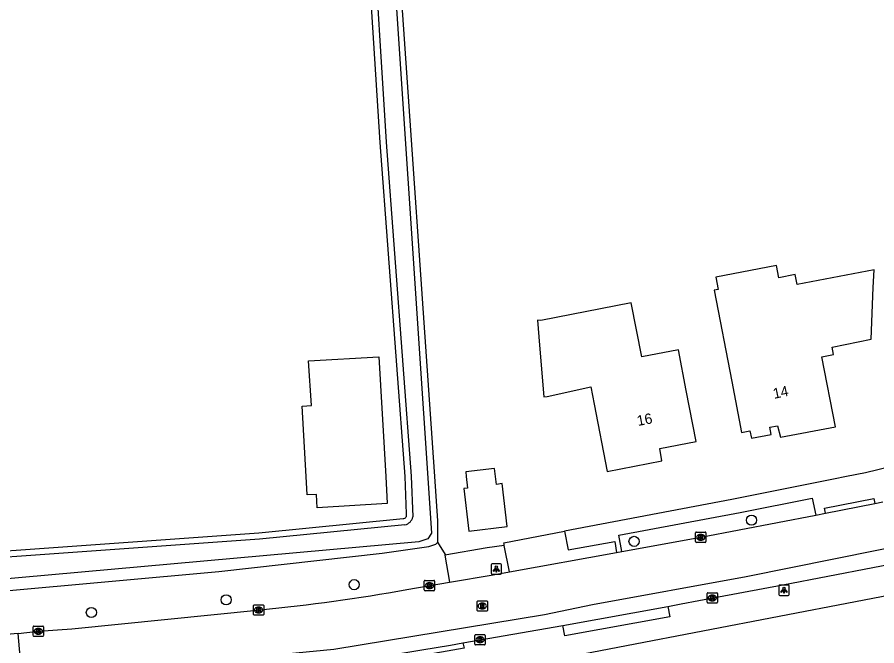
# Model space of a CAD drawing. Extents: x 161772 to 163123, y 383092 to 383917.
# Drawn here: x 162121.3 to 162204.2, y 383483.7 to 383544.3 of the extents above; entities that cross this region are included whole.
import ezdxf

# ---------------------------------------------------------------- set-up
doc = ezdxf.new("R2010")
doc.units = 0
for name, color, linetype in [('IMGEO_Boom', 7, 'Continuous'), ('IMGEO_Erf', 7, 'Continuous'), ('IMGEO_Groenvoorziening', 7, 'Continuous'), ('IMGEO_Kolk', 7, 'Continuous'), ('IMGEO_Lichtpunt', 7, 'Continuous'), ('IMGEO_Pand', 7, 'Continuous'), ('IMGEO_Pand_nummerreeks', 7, 'Continuous'), ('IMGEO_Rijbaan_lokaal_gesloten', 7, 'Continuous'), ('IMGEO_Rijbaan_lokaal_open', 7, 'Continuous'), ('IMGEO_Rioolput', 7, 'Continuous'), ('IMGEO_Voetpad_gesloten', 7, 'Continuous'), ('IMGEO_Voetpad_open', 7, 'Continuous'), ('IMGEO_Waterloop', 7, 'Continuous')]:
    doc.layers.add(name, color=color, linetype=linetype)

msp = doc.modelspace()

# ---------------------------------------------------------------- linework, layer by layer
at = {"layer": 'IMGEO_Boom'}
for centre in [(162192.143, 383495.789), (162180.807, 383493.753), (162153.81, 383489.576), (162141.449, 383488.119), (162128.443, 383486.899)]:
    msp.add_circle(centre, 0.489, dxfattribs=at)
at = {"layer": 'IMGEO_Erf'}
for points in [[(162161.876, 383493.674), (162161.877, 383495.743), (162161.582, 383500), (162158.081, 383550.584), (162157.485, 383556.946), (162155.147, 383589.879), (162154.233, 383609.363)], [(162158.844, 383496.393), (162158.71, 383500), (162156.297, 383532.223), (162154.911, 383554.445), (162150.941, 383605.06)], [(162069.536, 383488.799), (162096.809, 383491.155), (162144.603, 383494.579), (162158.53, 383495.946)]]:
    msp.add_lwpolyline(points, dxfattribs=at)
msp.add_arc((162158.525, 383496.283), 0.337, 270.78389, 19.04303, dxfattribs=at)
at = {"layer": 'IMGEO_Groenvoorziening'}
for points in [[(162062.506, 383483.909), (162085.683, 383486.129), (162109.132, 383487.972), (162140.737, 383490.84), (162156.508, 383492.599), (162160.992, 383493.243), (162161.691, 383493.467), (162161.876, 383493.674)], [(162162.551, 383492.413), (162162.614, 383492.483), (162161.876, 383493.674)]]:
    msp.add_lwpolyline(points, dxfattribs=at)
at = {"layer": 'IMGEO_Kolk'}
for p, q in [((162186.747, 383493.724), (162186.747, 383494.576)), ((162186.822, 383494.65), (162187.674, 383494.65)), ((162187.235, 383494.43), (162187.26, 383494.43)), ((162187.748, 383494.576), (162187.748, 383493.724)), ((162187.674, 383493.65), (162186.822, 383493.65)), ((162187.258, 383493.87), (162187.233, 383493.87)), ((162160.566, 383489.065), (162160.566, 383489.917)), ((162160.641, 383489.991), (162161.493, 383489.991)), ((162161.054, 383489.771), (162161.079, 383489.771)), ((162161.567, 383489.917), (162161.567, 383489.065)), ((162161.493, 383488.991), (162160.641, 383488.991)), ((162161.077, 383489.211), (162161.052, 383489.211)), ((162187.858, 383487.873), (162187.858, 383488.725)), ((162187.933, 383488.799), (162188.785, 383488.799)), ((162188.346, 383488.579), (162188.371, 383488.579)), ((162188.859, 383488.725), (162188.859, 383487.873)), ((162144.157, 383487.633), (162145.009, 383487.633)), ((162188.785, 383487.799), (162187.933, 383487.799)), ((162188.369, 383488.019), (162188.344, 383488.019)), ((162144.082, 383486.707), (162144.082, 383487.559)), ((162144.593, 383486.853), (162144.568, 383486.853)), ((162144.57, 383487.413), (162144.595, 383487.413)), ((162145.083, 383487.559), (162145.083, 383486.707)), ((162145.009, 383486.633), (162144.157, 383486.633)), ((162122.826, 383484.657), (162122.826, 383485.509)), ((162122.901, 383485.583), (162123.753, 383485.583)), ((162123.314, 383485.363), (162123.339, 383485.363)), ((162123.827, 383485.509), (162123.827, 383484.657)), ((162123.753, 383484.583), (162122.901, 383484.583)), ((162123.337, 383484.803), (162123.312, 383484.803)), ((162165.445, 383483.833), (162165.445, 383484.685)), ((162165.52, 383484.759), (162166.372, 383484.759)), ((162165.933, 383484.539), (162165.958, 383484.539)), ((162166.446, 383484.685), (162166.446, 383483.833)), ((162166.372, 383483.759), (162165.52, 383483.759)), ((162165.956, 383483.979), (162165.931, 383483.979))]:
    msp.add_line(p, q, dxfattribs=at)
for points in [[(162186.747, 383493.724), (162186.747, 383494.576)], [(162186.822, 383494.65), (162187.674, 383494.65)], [(162187.068, 383494.35), (162187.191, 383494.35), (162187.191, 383494.199), (162187.321, 383494.35), (162187.485, 383494.35), (162187.339, 383494.199), (162187.492, 383493.95), (162187.34, 383493.95), (162187.255, 383494.114), (162187.191, 383494.047), (162187.191, 383493.95), (162187.068, 383493.95), (162187.068, 383494.35)], [(162187.748, 383494.576), (162187.748, 383493.724)], [(162187.674, 383493.65), (162186.822, 383493.65)], [(162160.566, 383489.065), (162160.566, 383489.917)], [(162160.641, 383489.991), (162161.493, 383489.991)], [(162160.887, 383489.691), (162161.01, 383489.691), (162161.01, 383489.54), (162161.14, 383489.691), (162161.304, 383489.691), (162161.158, 383489.54), (162161.311, 383489.291), (162161.159, 383489.291), (162161.074, 383489.455), (162161.01, 383489.388), (162161.01, 383489.291), (162160.887, 383489.291), (162160.887, 383489.691)], [(162161.567, 383489.917), (162161.567, 383489.065)], [(162161.493, 383488.991), (162160.641, 383488.991)], [(162187.858, 383487.873), (162187.858, 383488.725)], [(162187.933, 383488.799), (162188.785, 383488.799)], [(162188.179, 383488.499), (162188.302, 383488.499), (162188.302, 383488.348), (162188.432, 383488.499), (162188.596, 383488.499), (162188.45, 383488.348), (162188.603, 383488.099), (162188.451, 383488.099), (162188.366, 383488.263), (162188.302, 383488.196), (162188.302, 383488.099), (162188.179, 383488.099), (162188.179, 383488.499)], [(162188.859, 383488.725), (162188.859, 383487.873)], [(162144.157, 383487.633), (162145.009, 383487.633)], [(162188.785, 383487.799), (162187.933, 383487.799)], [(162144.082, 383486.707), (162144.082, 383487.559)], [(162144.403, 383487.333), (162144.526, 383487.333), (162144.526, 383487.182), (162144.656, 383487.333), (162144.82, 383487.333), (162144.674, 383487.182), (162144.827, 383486.933), (162144.675, 383486.933), (162144.59, 383487.097), (162144.526, 383487.03), (162144.526, 383486.933), (162144.403, 383486.933), (162144.403, 383487.333)], [(162145.083, 383487.559), (162145.083, 383486.707)], [(162145.009, 383486.633), (162144.157, 383486.633)], [(162122.826, 383484.657), (162122.826, 383485.509)], [(162122.901, 383485.583), (162123.753, 383485.583)], [(162123.147, 383485.283), (162123.27, 383485.283), (162123.27, 383485.132), (162123.4, 383485.283), (162123.564, 383485.283), (162123.418, 383485.132), (162123.571, 383484.883), (162123.419, 383484.883), (162123.334, 383485.047), (162123.27, 383484.98), (162123.27, 383484.883), (162123.147, 383484.883), (162123.147, 383485.283)], [(162123.827, 383485.509), (162123.827, 383484.657)], [(162123.753, 383484.583), (162122.901, 383484.583)], [(162165.445, 383483.833), (162165.445, 383484.685)], [(162165.52, 383484.759), (162166.372, 383484.759)], [(162165.766, 383484.459), (162165.889, 383484.459), (162165.889, 383484.308), (162166.019, 383484.459), (162166.183, 383484.459), (162166.037, 383484.308), (162166.19, 383484.059), (162166.038, 383484.059), (162165.953, 383484.223), (162165.889, 383484.156), (162165.889, 383484.059), (162165.766, 383484.059), (162165.766, 383484.459)], [(162166.446, 383484.685), (162166.446, 383483.833)], [(162166.372, 383483.759), (162165.52, 383483.759)]]:
    msp.add_lwpolyline(points, dxfattribs=at)
for centre, start, end in [((162186.824, 383494.574), 91.55205, 178.44795), ((162186.824, 383494.574), 91.55205, 178.44795), ((162187.672, 383494.574), 1.55205, 88.44795), ((162187.672, 383494.574), 1.55205, 88.44795), ((162186.824, 383493.726), 181.55205, 268.44795), ((162186.824, 383493.726), 181.55205, 268.44795), ((162187.672, 383493.726), 271.55205, 358.44795), ((162187.672, 383493.726), 271.55205, 358.44795), ((162160.643, 383489.915), 91.55205, 178.44795), ((162160.643, 383489.915), 91.55205, 178.44795), ((162161.491, 383489.915), 1.55205, 88.44795), ((162161.491, 383489.915), 1.55205, 88.44795), ((162160.643, 383489.067), 181.55205, 268.44795), ((162160.643, 383489.067), 181.55205, 268.44795), ((162161.491, 383489.067), 271.55205, 358.44795), ((162161.491, 383489.067), 271.55205, 358.44795), ((162187.935, 383488.723), 91.55205, 178.44795), ((162187.935, 383488.723), 91.55205, 178.44795), ((162188.783, 383488.723), 1.55205, 88.44795), ((162188.783, 383488.723), 1.55205, 88.44795), ((162144.159, 383487.557), 91.55205, 178.44795), ((162144.159, 383487.557), 91.55205, 178.44795), ((162145.007, 383487.557), 1.55205, 88.44795), ((162145.007, 383487.557), 1.55205, 88.44795), ((162187.935, 383487.875), 181.55205, 268.44795), ((162187.935, 383487.875), 181.55205, 268.44795), ((162188.783, 383487.875), 271.55205, 358.44795), ((162188.783, 383487.875), 271.55205, 358.44795), ((162144.159, 383486.709), 181.55205, 268.44795), ((162144.159, 383486.709), 181.55205, 268.44795), ((162145.007, 383486.709), 271.55205, 358.44795), ((162145.007, 383486.709), 271.55205, 358.44795), ((162122.903, 383485.507), 91.55205, 178.44795), ((162122.903, 383485.507), 91.55205, 178.44795), ((162123.751, 383485.507), 1.55205, 88.44795), ((162123.751, 383485.507), 1.55205, 88.44795), ((162122.903, 383484.659), 181.55205, 268.44795), ((162122.903, 383484.659), 181.55205, 268.44795), ((162123.751, 383484.659), 271.55205, 358.44795), ((162123.751, 383484.659), 271.55205, 358.44795), ((162165.522, 383484.683), 91.55205, 178.44795), ((162165.522, 383484.683), 91.55205, 178.44795), ((162166.37, 383484.683), 1.55205, 88.44795), ((162166.37, 383484.683), 1.55205, 88.44795), ((162165.522, 383483.835), 181.55205, 268.44795), ((162165.522, 383483.835), 181.55205, 268.44795), ((162166.37, 383483.835), 271.55205, 358.44795), ((162166.37, 383483.835), 271.55205, 358.44795)]:
    msp.add_arc(centre, 0.0765, start, end, dxfattribs=at)
for centre, major_axis, ratio, start_param, end_param in [((162187.234, 383494.15), (-0.387, 0.002), 0.722429, 4.712389, 7.853982), ((162187.259, 383494.15), (-0.39, 0.002), 0.717154, 1.570796, 4.712389), ((162161.053, 383489.491), (-0.387, 0.002), 0.722429, 4.712389, 7.853982), ((162161.078, 383489.491), (-0.39, 0.002), 0.717154, 1.570796, 4.712389), ((162188.345, 383488.299), (-0.387, 0.002), 0.722429, 4.712389, 7.853982), ((162188.37, 383488.299), (-0.39, 0.002), 0.717154, 1.570796, 4.712389), ((162144.569, 383487.133), (-0.387, 0.002), 0.722429, 4.712389, 7.853982), ((162144.594, 383487.133), (-0.39, 0.002), 0.717154, 1.570796, 4.712389), ((162123.313, 383485.083), (-0.387, 0.002), 0.722429, 4.712389, 7.853982), ((162123.338, 383485.083), (-0.39, 0.002), 0.717154, 1.570796, 4.712389), ((162165.932, 383484.259), (-0.387, 0.002), 0.722429, 4.712389, 7.853982), ((162165.957, 383484.259), (-0.39, 0.002), 0.717154, 1.570796, 4.712389)]:
    msp.add_ellipse(centre, major_axis=major_axis, ratio=ratio, start_param=start_param, end_param=end_param, dxfattribs=at)
at = {"layer": 'IMGEO_Lichtpunt'}
for p, q in [((162167.02, 383491.479), (162167.02, 383490.672)), ((162167.02, 383491.479), (162167.02, 383490.672)), ((162167.922, 383491.574), (162167.114, 383491.574)), ((162167.922, 383491.574), (162167.114, 383491.574)), ((162168.016, 383490.672), (162168.016, 383491.479)), ((162168.016, 383490.672), (162168.016, 383491.479)), ((162167.114, 383490.578), (162167.922, 383490.578)), ((162167.114, 383490.578), (162167.922, 383490.578)), ((162194.775, 383489.447), (162194.775, 383488.64)), ((162194.775, 383489.447), (162194.775, 383488.64)), ((162195.677, 383489.542), (162194.869, 383489.542)), ((162195.677, 383489.542), (162194.869, 383489.542)), ((162195.771, 383488.64), (162195.771, 383489.447)), ((162195.771, 383488.64), (162195.771, 383489.447)), ((162194.869, 383488.546), (162195.677, 383488.546)), ((162194.869, 383488.546), (162195.677, 383488.546))]:
    msp.add_line(p, q, dxfattribs=at)
for points in [[(162167.394, 383491.143), (162167.433, 383491.115), (162167.245, 383490.853), (162167.207, 383490.88), (162167.394, 383491.143)], [(162167.496, 383491.095), (162167.543, 383491.095), (162167.543, 383490.773), (162167.496, 383490.773), (162167.496, 383491.095)], [(162167.606, 383491.115), (162167.644, 383491.142), (162167.831, 383490.88), (162167.792, 383490.852), (162167.606, 383491.115)], [(162195.149, 383489.111), (162195.188, 383489.083), (162195, 383488.821), (162194.962, 383488.848), (162195.149, 383489.111)], [(162195.251, 383489.063), (162195.298, 383489.063), (162195.298, 383488.741), (162195.251, 383488.741), (162195.251, 383489.063)], [(162195.361, 383489.083), (162195.399, 383489.11), (162195.586, 383488.848), (162195.547, 383488.82), (162195.361, 383489.083)]]:
    msp.add_lwpolyline(points, dxfattribs=at)
for centre in [(162167.519, 383491.277), (162195.274, 383489.245)]:
    msp.add_circle(centre, 0.0994, dxfattribs=at)
for centre, start, end in [((162167.114, 383491.479), 90, 180), ((162167.114, 383491.479), 90, 180), ((162167.922, 383491.479), 0, 90), ((162167.922, 383491.479), 0, 90), ((162167.114, 383490.672), 180, 270), ((162167.114, 383490.672), 180, 270), ((162167.922, 383490.672), 270, 0), ((162167.922, 383490.672), 270, 360), ((162194.869, 383489.447), 90, 180), ((162194.869, 383489.447), 90, 180), ((162195.677, 383489.447), 0, 90), ((162195.677, 383489.447), 0, 90), ((162194.869, 383488.64), 180, 270), ((162194.869, 383488.64), 180, 270), ((162195.677, 383488.64), 270, 0), ((162195.677, 383488.64), 270, 360)]:
    msp.add_arc(centre, 0.0946, start, end, dxfattribs=at)
at = {"layer": 'IMGEO_Pand'}
for points in [[(162203.893, 383518.235), (162203.962, 383519.946), (162196.537, 383518.512), (162196.349, 383519.481), (162194.771, 383519.177), (162194.542, 383520.361), (162188.713, 383519.235), (162188.94, 383518.049), (162188.538, 383517.972), (162190.237, 383509.166), (162191.185, 383504.256), (162191.973, 383504.406), (162192.152, 383503.708), (162194.049, 383504.071), (162193.909, 383504.783), (162194.64, 383504.894), (162194.94, 383503.789), (162200.24, 383504.802), (162198.917, 383511.548), (162200.059, 383511.769), (162199.928, 383512.488), (162203.69, 383513.239), (162203.893, 383518.235)], [(162176.966, 383506.995), (162178.211, 383500.507), (162183.504, 383501.529), (162183.298, 383502.704), (162186.803, 383503.392), (162185.849, 383508.301), (162185.086, 383512.224), (162181.554, 383511.537), (162180.541, 383516.748), (162171.827, 383515.057), (162171.503, 383515.098), (162171.697, 383512.672), (162172.096, 383507.687), (162172.418, 383507.711), (162176.65, 383508.642), (162176.966, 383506.995)], [(162149.154, 383500), (162148.774, 383506.794), (162149.672, 383506.849), (162149.406, 383511.15), (162156.178, 383511.559), (162156.85, 383500), (162157, 383497.415), (162150.232, 383496.997), (162150.152, 383498.284), (162149.253, 383498.228), (162149.154, 383500)], [(162164.377, 383498.843), (162164.861, 383494.748), (162168.577, 383495.187), (162168.09, 383499.318), (162167.531, 383499.252), (162167.444, 383500), (162167.352, 383500.783), (162164.569, 383500.454), (162164.622, 383500), (162164.753, 383498.888), (162164.377, 383498.843)]]:
    msp.add_lwpolyline(points, dxfattribs=at)
at = {"layer": 'IMGEO_Rijbaan_lokaal_gesloten'}
for points in [[(162199.296, 383496.468), (162204.046, 383497.404)], [(162204.046, 383497.404), (162204.798, 383497.552)], [(162179.624, 383492.766), (162187.245, 383494.148), (162198.338, 383496.284)], [(162198.338, 383496.284), (162199.296, 383496.468)], [(162213.84, 383494.742), (162208.551, 383493.75), (162191.634, 383490.333), (162176.787, 383487.642), (162172.161, 383486.674), (162151.828, 383483.337), (162127.505, 383480.969), (162121.767, 383480.433)], [(162168.781, 383490.815), (162179.124, 383492.675)], [(162179.124, 383492.675), (162179.624, 383492.766)], [(162163.009, 383489.813), (162167.216, 383490.539), (162168.781, 383490.815)], [(162158.883, 383489.1), (162163.009, 383489.813)], [(162121.373, 383484.872), (162123.327, 383485.081), (162126.573, 383485.331), (162144.748, 383487.15)]]:
    msp.add_lwpolyline(points, dxfattribs=at)
msp.add_arc((162126.484, 383671.743), 185.494, 275.65044, 280.05893, dxfattribs=at)
at = {"layer": 'IMGEO_Rijbaan_lokaal_open'}
for points in [[(162121.373, 383484.872), (162101.898, 383483.2)], [(162121.767, 383480.433), (162121.373, 383484.872)]]:
    msp.add_lwpolyline(points, dxfattribs=at)
at = {"layer": 'IMGEO_Rioolput'}
for p, q in [((162165.664, 383487.095), (162165.664, 383487.947)), ((162165.739, 383488.021), (162166.591, 383488.021)), ((162166.152, 383487.801), (162166.177, 383487.801)), ((162166.665, 383487.947), (162166.665, 383487.095)), ((162166.591, 383487.021), (162165.739, 383487.021)), ((162166.175, 383487.241), (162166.15, 383487.241))]:
    msp.add_line(p, q, dxfattribs=at)
for points in [[(162165.664, 383487.095), (162165.664, 383487.947)], [(162165.739, 383488.021), (162166.591, 383488.021)], [(162166.253, 383487.719), (162166.001, 383487.721), (162166.001, 383487.321)], [(162166.179, 383487.64), (162166.125, 383487.64), (162166.125, 383487.559)], [(162166.665, 383487.947), (162166.665, 383487.095)], [(162166.591, 383487.021), (162165.739, 383487.021)], [(162166.001, 383487.321), (162166.125, 383487.321), (162166.125, 383487.483), (162166.136, 383487.483)], [(162166.125, 383487.559), (162166.177, 383487.559)], [(162166.183, 383487.454), (162166.254, 383487.321), (162166.394, 383487.321), (162166.329, 383487.447)]]:
    msp.add_lwpolyline(points, dxfattribs=at)
for centre, radius, start, end in [((162165.741, 383487.945), 0.0765, 91.55205, 178.44795), ((162165.741, 383487.945), 0.0765, 91.55205, 178.44795), ((162166.185, 383487.544), 0.0964, 77.00612, 93.18647), ((162166.199, 383487.601), 0.0378, 276.66336, 79.67722), ((162166.252, 383487.609), 0.109, 350.36119, 89.41601), ((162166.589, 383487.945), 0.0765, 1.55205, 88.44795), ((162166.589, 383487.945), 0.0765, 1.55205, 88.44795), ((162165.741, 383487.097), 0.0765, 181.55205, 268.44795), ((162165.741, 383487.097), 0.0765, 181.55205, 268.44795), ((162166.135, 383487.43), 0.0533, 26.02933, 88.69889), ((162166.161, 383487.748), 0.19, 274.7715, 282.96867), ((162166.25, 383487.609), 0.112, 277.58423, 350.98172), ((162166.234, 383487.394), 0.108, 29.51342, 73.79051), ((162166.589, 383487.097), 0.0765, 271.55205, 358.44795), ((162166.589, 383487.097), 0.0765, 271.55205, 358.44795)]:
    msp.add_arc(centre, radius, start, end, dxfattribs=at)
for centre, major_axis, ratio, start_param, end_param in [((162166.151, 383487.521), (-0.387, 0.002), 0.722429, 4.712389, 7.853982), ((162166.176, 383487.521), (-0.39, 0.002), 0.717154, 1.570796, 4.712389)]:
    msp.add_ellipse(centre, major_axis=major_axis, ratio=ratio, start_param=start_param, end_param=end_param, dxfattribs=at)
at = {"layer": 'IMGEO_Voetpad_gesloten'}
for points in [[(162238.094, 383508.962), (162207.786, 383501.489), (162203.129, 383500.365), (162201.315, 383500), (162200.042, 383499.744), (162190.237, 383497.796), (162174.097, 383494.735)], [(162179.624, 383492.766), (162179.346, 383494.345), (162191.055, 383496.548), (162198.009, 383497.93), (162198.338, 383496.284)], [(162199.296, 383496.468), (162199.2, 383496.958), (162203.95, 383497.894), (162204.046, 383497.404)], [(162174.097, 383494.735), (162174.435, 383492.923), (162178.945, 383493.739), (162179.124, 383492.675)]]:
    msp.add_lwpolyline(points, dxfattribs=at)
at = {"layer": 'IMGEO_Voetpad_open'}
for points in [[(162168.284, 383493.357), (162168.26, 383493.478), (162168.232, 383493.623), (162174.097, 383494.735)], [(162168.284, 383493.357), (162166.643, 383493.113), (162162.551, 383492.413)], [(162168.781, 383490.815), (162168.284, 383493.357)], [(162184.063, 383487.456), (162185.341, 383487.72), (162187.046, 383488.051), (162195.161, 383489.557), (162208.205, 383492.066), (162211.371, 383492.687)], [(162162.551, 383492.413), (162163.009, 383489.813)], [(162216.905, 383490.741), (162172.706, 383482.249), (162150.151, 383478.81), (162136.452, 383477.299), (162125.335, 383475.754)], [(162173.933, 383485.639), (162184.063, 383487.456)], [(162184.063, 383487.456), (162184.246, 383486.462), (162174.144, 383484.646), (162173.933, 383485.639)], [(162164.302, 383483.975), (162173.933, 383485.639)], [(162155.726, 383482.506), (162160.337, 383483.275), (162163.109, 383483.74), (162164.302, 383483.975)], [(162164.302, 383483.975), (162164.412, 383483.464), (162155.826, 383481.943), (162155.726, 383482.506)]]:
    msp.add_lwpolyline(points, dxfattribs=at)
at = {"layer": 'IMGEO_Waterloop'}
for points in [[(162027.929, 383608.597), (162072.515, 383610.975), (162118.63, 383611.484), (162148.651, 383610.678), (162151.666, 383610.465), (162152.982, 383610.083), (162153.492, 383609.319), (162153.662, 383608.215), (162161.262, 383494.542), (162160.923, 383493.99), (162160.031, 383493.693), (162065.211, 383485.2), (162063.853, 383486.304), (162064.277, 383488.087), (162064.702, 383489.446), (162062.749, 383509.744), (162063.853, 383512.376), (162062.494, 383535.221), (162057.059, 383607.323), (162056.209, 383607.599), (162054.214, 383607.493), (162027.929, 383606.495), (162027.929, 383608.597)], [(162151.532, 383605.239), (162155.513, 383554.487), (162156.899, 383532.264), (162159.313, 383500.034), (162159.452, 383496.112)], [(162158.699, 383495.356), (162144.654, 383493.978), (162096.857, 383490.553), (162069.532, 383488.193)]]:
    msp.add_lwpolyline(points, dxfattribs=at)
msp.add_arc((162158.527, 383496.281), 0.94, 280.55367, 349.67415, dxfattribs=at)

# ---------------------------------------------------------------- texts
at = {"layer": 'IMGEO_Pand_nummerreeks'}
for s, rotation, p in [('14', 11.94052, (162194.323, 383507.495)), ('16', 10.91202, (162181.186, 383504.875))]:
    msp.add_text(s, height=1, rotation=rotation, dxfattribs=at).set_placement(p)

doc.saveas('drawing.dxf')
